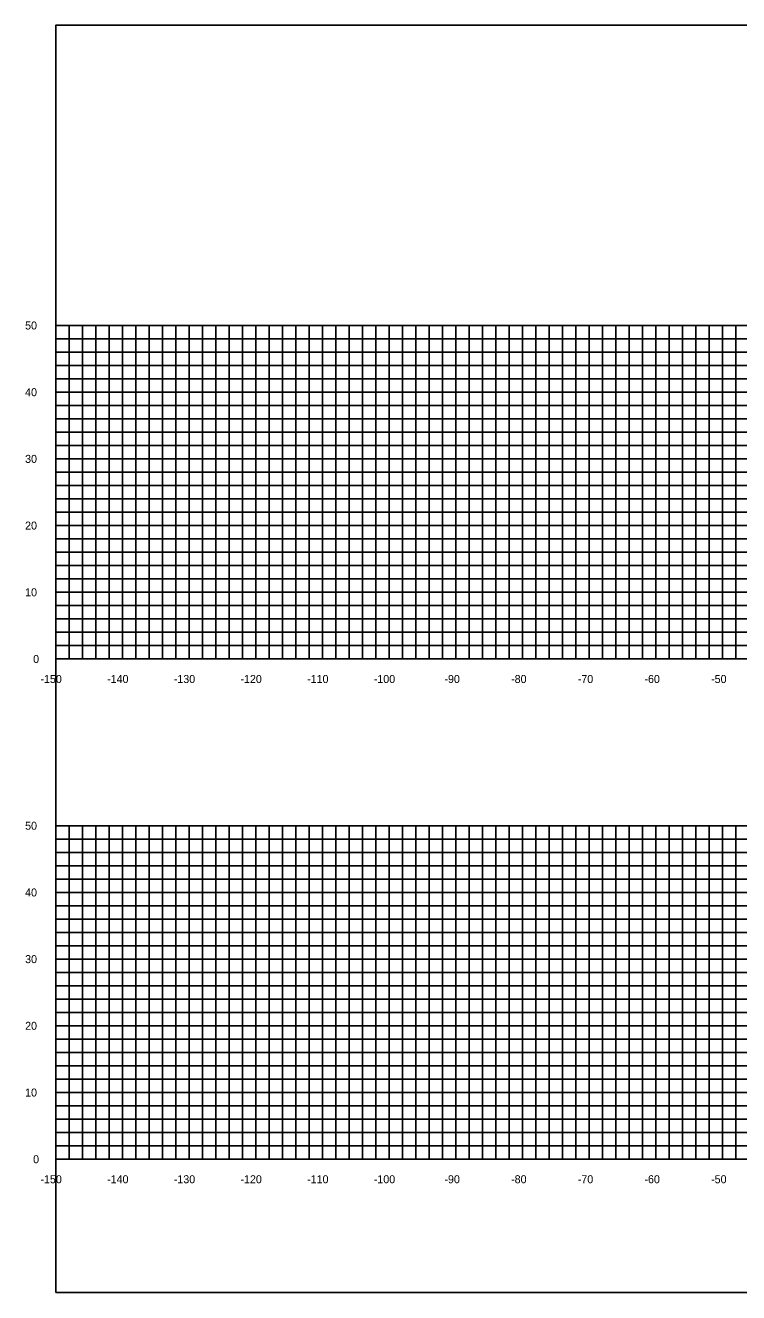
# Model space of a CAD drawing. Extents: x 1797714 to 1804825, y 249015 to 250269.
# Drawn here: x 1802789.6 to 1802896.6, y 249628.2 to 249818.2 of the extents above; entities that cross this region are included whole.
import ezdxf

# ---------------------------------------------------------------- set-up
doc = ezdxf.new("R2010")
doc.units = 0
for name, color, linetype in [('10', 7, 'Continuous'), ('31', 7, 'Continuous'), ('60', 7, 'Continuous'), ('Level 62', 7, 'Continuous')]:
    doc.layers.add(name, color=color, linetype=linetype)

msp = doc.modelspace()

# ---------------------------------------------------------------- linework, layer by layer
msp.add_lwpolyline([(1802794.16, 249628.17), (1803094.16, 249628.17), (1803094.16, 249818.17), (1802794.16, 249818.17)], close=True)
at = {"layer": '60'}
for p, q in [((1802794.1, 249773.17), (1802794.16, 249773.17)), ((1802794.16, 249723.17), (1802794.16, 249773.17)), ((1802794.1, 249763.17), (1802794.16, 249763.17)), ((1802794.1, 249753.17), (1802794.16, 249753.17)), ((1802794.1, 249743.17), (1802794.16, 249743.17)), ((1802794.1, 249733.17), (1802794.16, 249733.17)), ((1802794.1, 249723.17), (1802794.16, 249723.17)), ((1802794.16, 249723.17), (1803094.16, 249723.17)), ((1802794.16, 249723.11), (1802794.16, 249723.17)), ((1802804.16, 249723.11), (1802804.16, 249723.17)), ((1802814.16, 249723.11), (1802814.16, 249723.17)), ((1802824.16, 249723.11), (1802824.16, 249723.17)), ((1802834.16, 249723.11), (1802834.16, 249723.17)), ((1802844.16, 249723.11), (1802844.16, 249723.17)), ((1802854.16, 249723.11), (1802854.16, 249723.17)), ((1802864.16, 249723.11), (1802864.16, 249723.17)), ((1802874.16, 249723.11), (1802874.16, 249723.17)), ((1802884.16, 249723.11), (1802884.16, 249723.17)), ((1802894.16, 249723.11), (1802894.16, 249723.17)), ((1802794.1, 249698.17), (1802794.16, 249698.17)), ((1802794.16, 249648.17), (1802794.16, 249698.17)), ((1802794.1, 249688.17), (1802794.16, 249688.17)), ((1802794.1, 249678.17), (1802794.16, 249678.17)), ((1802794.1, 249668.17), (1802794.16, 249668.17)), ((1802794.1, 249658.17), (1802794.16, 249658.17)), ((1802794.1, 249648.17), (1802794.16, 249648.17)), ((1802794.16, 249648.17), (1803094.16, 249648.17)), ((1802794.16, 249648.11), (1802794.16, 249648.17)), ((1802804.16, 249648.11), (1802804.16, 249648.17)), ((1802814.16, 249648.11), (1802814.16, 249648.17)), ((1802824.16, 249648.11), (1802824.16, 249648.17)), ((1802834.16, 249648.11), (1802834.16, 249648.17)), ((1802844.16, 249648.11), (1802844.16, 249648.17)), ((1802854.16, 249648.11), (1802854.16, 249648.17)), ((1802864.16, 249648.11), (1802864.16, 249648.17)), ((1802874.16, 249648.11), (1802874.16, 249648.17)), ((1802884.16, 249648.11), (1802884.16, 249648.17)), ((1802894.16, 249648.11), (1802894.16, 249648.17))]:
    msp.add_line(p, q, dxfattribs=at)
at = {"layer": 'Level 62'}
for p, q in [((1802794.16, 249773.17), (1803094.16, 249773.17)), ((1802794.16, 249723.17), (1802794.16, 249773.17)), ((1802796.16, 249723.17), (1802796.16, 249773.17)), ((1802798.16, 249723.17), (1802798.16, 249773.17)), ((1802800.16, 249723.17), (1802800.16, 249773.17)), ((1802802.16, 249723.17), (1802802.16, 249773.17)), ((1802804.16, 249723.17), (1802804.16, 249773.17)), ((1802806.16, 249723.17), (1802806.16, 249773.17)), ((1802808.16, 249723.17), (1802808.16, 249773.17)), ((1802810.16, 249723.17), (1802810.16, 249773.17)), ((1802812.16, 249723.17), (1802812.16, 249773.17)), ((1802814.16, 249723.17), (1802814.16, 249773.17)), ((1802816.16, 249723.17), (1802816.16, 249773.17)), ((1802818.16, 249723.17), (1802818.16, 249773.17)), ((1802820.16, 249723.17), (1802820.16, 249773.17)), ((1802822.16, 249723.17), (1802822.16, 249773.17)), ((1802824.16, 249723.17), (1802824.16, 249773.17)), ((1802826.16, 249723.17), (1802826.16, 249773.17)), ((1802828.16, 249723.17), (1802828.16, 249773.17)), ((1802830.16, 249723.17), (1802830.16, 249773.17)), ((1802832.16, 249723.17), (1802832.16, 249773.17)), ((1802834.16, 249723.17), (1802834.16, 249773.17)), ((1802836.16, 249723.17), (1802836.16, 249773.17)), ((1802838.16, 249723.17), (1802838.16, 249773.17)), ((1802840.16, 249723.17), (1802840.16, 249773.17)), ((1802842.16, 249723.17), (1802842.16, 249773.17)), ((1802844.16, 249723.17), (1802844.16, 249773.17)), ((1802846.16, 249723.17), (1802846.16, 249773.17)), ((1802848.16, 249723.17), (1802848.16, 249773.17)), ((1802850.16, 249723.17), (1802850.16, 249773.17)), ((1802852.16, 249723.17), (1802852.16, 249773.17)), ((1802854.16, 249723.17), (1802854.16, 249773.17)), ((1802856.16, 249723.17), (1802856.16, 249773.17)), ((1802858.16, 249723.17), (1802858.16, 249773.17)), ((1802860.16, 249723.17), (1802860.16, 249773.17)), ((1802862.16, 249723.17), (1802862.16, 249773.17)), ((1802864.16, 249723.17), (1802864.16, 249773.17)), ((1802866.16, 249723.17), (1802866.16, 249773.17)), ((1802868.16, 249723.17), (1802868.16, 249773.17)), ((1802870.16, 249723.17), (1802870.16, 249773.17)), ((1802872.16, 249723.17), (1802872.16, 249773.17)), ((1802874.16, 249723.17), (1802874.16, 249773.17)), ((1802876.16, 249723.17), (1802876.16, 249773.17)), ((1802878.16, 249723.17), (1802878.16, 249773.17)), ((1802880.16, 249723.17), (1802880.16, 249773.17)), ((1802882.16, 249723.17), (1802882.16, 249773.17)), ((1802884.16, 249723.17), (1802884.16, 249773.17)), ((1802886.16, 249723.17), (1802886.16, 249773.17)), ((1802888.16, 249723.17), (1802888.16, 249773.17)), ((1802890.16, 249723.17), (1802890.16, 249773.17)), ((1802892.16, 249723.17), (1802892.16, 249773.17)), ((1802894.16, 249723.17), (1802894.16, 249773.17)), ((1802896.16, 249723.17), (1802896.16, 249773.17)), ((1802794.16, 249771.17), (1803094.16, 249771.17)), ((1802794.16, 249769.17), (1803094.16, 249769.17)), ((1802794.16, 249767.17), (1803094.16, 249767.17)), ((1802794.16, 249765.17), (1803094.16, 249765.17)), ((1802794.16, 249763.17), (1803094.16, 249763.17)), ((1802794.16, 249761.17), (1803094.16, 249761.17)), ((1802794.16, 249759.17), (1803094.16, 249759.17)), ((1802794.16, 249757.17), (1803094.16, 249757.17)), ((1802794.16, 249755.17), (1803094.16, 249755.17)), ((1802794.16, 249753.17), (1803094.16, 249753.17)), ((1802794.16, 249751.17), (1803094.16, 249751.17)), ((1802794.16, 249749.17), (1803094.16, 249749.17)), ((1802794.16, 249747.17), (1803094.16, 249747.17)), ((1802794.16, 249745.17), (1803094.16, 249745.17)), ((1802794.16, 249743.17), (1803094.16, 249743.17)), ((1802794.16, 249741.17), (1803094.16, 249741.17)), ((1802794.16, 249739.17), (1803094.16, 249739.17)), ((1802794.16, 249737.17), (1803094.16, 249737.17)), ((1802794.16, 249735.17), (1803094.16, 249735.17)), ((1802794.16, 249733.17), (1803094.16, 249733.17)), ((1802794.16, 249731.17), (1803094.16, 249731.17)), ((1802794.16, 249729.17), (1803094.16, 249729.17)), ((1802794.16, 249727.17), (1803094.16, 249727.17)), ((1802794.16, 249725.17), (1803094.16, 249725.17)), ((1802794.16, 249723.17), (1803094.16, 249723.17)), ((1802794.16, 249698.17), (1803094.16, 249698.17)), ((1802794.16, 249648.17), (1802794.16, 249698.17)), ((1802796.16, 249648.17), (1802796.16, 249698.17)), ((1802798.16, 249648.17), (1802798.16, 249698.17)), ((1802800.16, 249648.17), (1802800.16, 249698.17)), ((1802802.16, 249648.17), (1802802.16, 249698.17)), ((1802804.16, 249648.17), (1802804.16, 249698.17)), ((1802806.16, 249648.17), (1802806.16, 249698.17)), ((1802808.16, 249648.17), (1802808.16, 249698.17)), ((1802810.16, 249648.17), (1802810.16, 249698.17)), ((1802812.16, 249648.17), (1802812.16, 249698.17)), ((1802814.16, 249648.17), (1802814.16, 249698.17)), ((1802816.16, 249648.17), (1802816.16, 249698.17)), ((1802818.16, 249648.17), (1802818.16, 249698.17)), ((1802820.16, 249648.17), (1802820.16, 249698.17)), ((1802822.16, 249648.17), (1802822.16, 249698.17)), ((1802824.16, 249648.17), (1802824.16, 249698.17)), ((1802826.16, 249648.17), (1802826.16, 249698.17)), ((1802828.16, 249648.17), (1802828.16, 249698.17)), ((1802830.16, 249648.17), (1802830.16, 249698.17)), ((1802832.16, 249648.17), (1802832.16, 249698.17)), ((1802834.16, 249648.17), (1802834.16, 249698.17)), ((1802836.16, 249648.17), (1802836.16, 249698.17)), ((1802838.16, 249648.17), (1802838.16, 249698.17)), ((1802840.16, 249648.17), (1802840.16, 249698.17)), ((1802842.16, 249648.17), (1802842.16, 249698.17)), ((1802844.16, 249648.17), (1802844.16, 249698.17)), ((1802846.16, 249648.17), (1802846.16, 249698.17)), ((1802848.16, 249648.17), (1802848.16, 249698.17)), ((1802850.16, 249648.17), (1802850.16, 249698.17)), ((1802852.16, 249648.17), (1802852.16, 249698.17)), ((1802854.16, 249648.17), (1802854.16, 249698.17)), ((1802856.16, 249648.17), (1802856.16, 249698.17)), ((1802858.16, 249648.17), (1802858.16, 249698.17)), ((1802860.16, 249648.17), (1802860.16, 249698.17)), ((1802862.16, 249648.17), (1802862.16, 249698.17)), ((1802864.16, 249648.17), (1802864.16, 249698.17)), ((1802866.16, 249648.17), (1802866.16, 249698.17)), ((1802868.16, 249648.17), (1802868.16, 249698.17)), ((1802870.16, 249648.17), (1802870.16, 249698.17)), ((1802872.16, 249648.17), (1802872.16, 249698.17)), ((1802874.16, 249648.17), (1802874.16, 249698.17)), ((1802876.16, 249648.17), (1802876.16, 249698.17)), ((1802878.16, 249648.17), (1802878.16, 249698.17)), ((1802880.16, 249648.17), (1802880.16, 249698.17)), ((1802882.16, 249648.17), (1802882.16, 249698.17)), ((1802884.16, 249648.17), (1802884.16, 249698.17)), ((1802886.16, 249648.17), (1802886.16, 249698.17)), ((1802888.16, 249648.17), (1802888.16, 249698.17)), ((1802890.16, 249648.17), (1802890.16, 249698.17)), ((1802892.16, 249648.17), (1802892.16, 249698.17)), ((1802894.16, 249648.17), (1802894.16, 249698.17)), ((1802896.16, 249648.17), (1802896.16, 249698.17)), ((1802794.16, 249696.17), (1803094.16, 249696.17)), ((1802794.16, 249694.17), (1803094.16, 249694.17)), ((1802794.16, 249692.17), (1803094.16, 249692.17)), ((1802794.16, 249690.17), (1803094.16, 249690.17)), ((1802794.16, 249688.17), (1803094.16, 249688.17)), ((1802794.16, 249686.17), (1803094.16, 249686.17)), ((1802794.16, 249684.17), (1803094.16, 249684.17)), ((1802794.16, 249682.17), (1803094.16, 249682.17)), ((1802794.16, 249680.17), (1803094.16, 249680.17)), ((1802794.16, 249678.17), (1803094.16, 249678.17)), ((1802794.16, 249676.17), (1803094.16, 249676.17)), ((1802794.16, 249674.17), (1803094.16, 249674.17)), ((1802794.16, 249672.17), (1803094.16, 249672.17)), ((1802794.16, 249670.17), (1803094.16, 249670.17)), ((1802794.16, 249668.17), (1803094.16, 249668.17)), ((1802794.16, 249666.17), (1803094.16, 249666.17)), ((1802794.16, 249664.17), (1803094.16, 249664.17)), ((1802794.16, 249662.17), (1803094.16, 249662.17)), ((1802794.16, 249660.17), (1803094.16, 249660.17)), ((1802794.16, 249658.17), (1803094.16, 249658.17)), ((1802794.16, 249656.17), (1803094.16, 249656.17)), ((1802794.16, 249654.17), (1803094.16, 249654.17)), ((1802794.16, 249652.17), (1803094.16, 249652.17)), ((1802794.16, 249650.17), (1803094.16, 249650.17)), ((1802794.16, 249648.17), (1803094.16, 249648.17))]:
    msp.add_line(p, q, dxfattribs=at)

# ---------------------------------------------------------------- texts
at = {"layer": '10'}
for s, p in [('-150', (1802791.86, 249719.57)), ('-140', (1802801.86, 249719.57)), ('-130', (1802811.86, 249719.57)), ('-120', (1802821.86, 249719.57)), ('-110', (1802831.86, 249719.57)), ('-100', (1802841.86, 249719.57)), ('-90', (1802852.46, 249719.57)), ('-80', (1802862.46, 249719.57)), ('-70', (1802872.46, 249719.57)), ('-60', (1802882.46, 249719.57)), ('-50', (1802892.46, 249719.57)), ('-150', (1802791.86, 249644.57)), ('-140', (1802801.86, 249644.57)), ('-130', (1802811.86, 249644.57)), ('-120', (1802821.86, 249644.57)), ('-110', (1802831.86, 249644.57)), ('-100', (1802841.86, 249644.57)), ('-90', (1802852.46, 249644.57)), ('-80', (1802862.46, 249644.57)), ('-70', (1802872.46, 249644.57)), ('-60', (1802882.46, 249644.57)), ('-50', (1802892.46, 249644.57))]:
    msp.add_text(s, height=1.2, dxfattribs=at).set_placement(p)
at = {"layer": '31'}
for s, p in [('50', (1802789.56, 249772.57)), ('40', (1802789.56, 249762.57)), ('30', (1802789.56, 249752.57)), ('20', (1802789.56, 249742.57)), ('10', (1802789.56, 249732.57)), ('0', (1802790.76, 249722.57)), ('50', (1802789.56, 249697.57)), ('40', (1802789.56, 249687.57)), ('30', (1802789.56, 249677.57)), ('20', (1802789.56, 249667.57)), ('10', (1802789.56, 249657.57)), ('0', (1802790.76, 249647.57))]:
    msp.add_text(s, height=1.2, dxfattribs=at).set_placement(p)
at = {"layer": '60'}
for p in [(1802794.16, 249723.17), (1802794.16, 249648.17)]:
    msp.add_text('-', height=0.0001, dxfattribs=at).set_placement(p)

doc.saveas('drawing.dxf')
